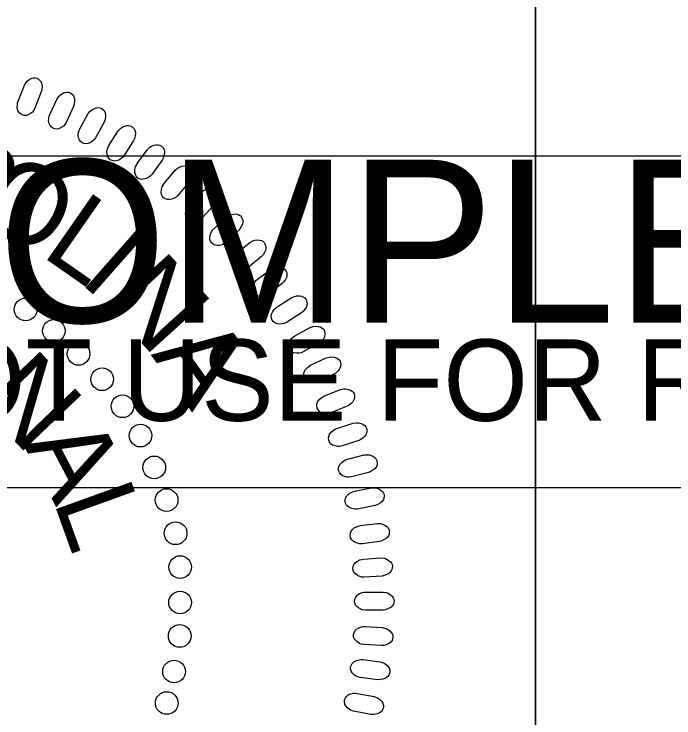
# Model space of a CAD drawing. Extents: x 505602 to 507705, y 483109 to 484209.
# Drawn here: x 507132.23 to 507178.88, y 484086.24 to 484136.03 of the extents above; entities that cross this region are included whole.
import ezdxf

# ---------------------------------------------------------------- set-up
doc = ezdxf.new("R2010")
doc.units = 0
for name, color, linetype in [('Sheet PE Seal Cell', 7, 'Continuous'), ('Sheet Profile CELL', 7, 'Continuous'), ('Sheet Sticker Incomplete CELL', 7, 'Continuous')]:
    doc.layers.add(name, color=color, linetype=linetype)

msp = doc.modelspace()

# ---------------------------------------------------------------- linework, layer by layer
at = {"layer": 'Sheet PE Seal Cell'}
for points in [[(507132.514, 484129.863), (507132.966, 484131.003), (507133.082, 484131.193), (507133.182, 484131.304), (507133.349, 484131.42), (507133.48, 484131.486), (507133.613, 484131.519), (507133.725, 484131.518), (507133.837, 484131.495), (507133.933, 484131.435), (507134.034, 484131.363), (507134.109, 484131.269), (507134.17, 484131.137), (507134.196, 484131.041), (507134.203, 484130.878), (507134.193, 484130.689), (507134.155, 484130.532), (507133.699, 484129.361), (507133.615, 484129.212), (507133.522, 484129.098), (507133.38, 484128.984), (507133.224, 484128.894), (507133.105, 484128.856), (507132.936, 484128.859), (507132.79, 484128.895), (507132.666, 484128.987), (507132.587, 484129.072), (507132.505, 484129.212), (507132.457, 484129.414), (507132.46, 484129.605), (507132.481, 484129.737)], [(507134.756, 484128.929), (507135.278, 484130.038), (507135.405, 484130.221), (507135.512, 484130.325), (507135.686, 484130.431), (507135.821, 484130.489), (507135.956, 484130.513), (507136.068, 484130.504), (507136.178, 484130.474), (507136.27, 484130.408), (507136.366, 484130.331), (507136.435, 484130.232), (507136.487, 484130.097), (507136.508, 484130), (507136.505, 484129.835), (507136.482, 484129.648), (507136.435, 484129.493), (507135.906, 484128.353), (507135.814, 484128.21), (507135.713, 484128.102), (507135.564, 484127.996), (507135.403, 484127.918), (507135.281, 484127.887), (507135.114, 484127.899), (507134.97, 484127.946), (507134.852, 484128.045), (507134.779, 484128.135), (507134.706, 484128.279), (507134.67, 484128.483), (507134.686, 484128.675), (507134.714, 484128.804)], [(507136.88, 484127.913), (507137.471, 484128.988), (507137.609, 484129.162), (507137.722, 484129.259), (507137.902, 484129.354), (507138.04, 484129.403), (507138.177, 484129.419), (507138.288, 484129.403), (507138.396, 484129.367), (507138.485, 484129.295), (507138.575, 484129.211), (507138.638, 484129.109), (507138.682, 484128.971), (507138.695, 484128.872), (507138.683, 484128.709), (507138.648, 484128.522), (507138.591, 484128.372), (507137.992, 484127.267), (507137.89, 484127.13), (507137.784, 484127.029), (507137.629, 484126.932), (507137.462, 484126.864), (507137.339, 484126.841), (507137.173, 484126.864), (507137.032, 484126.919), (507136.92, 484127.025), (507136.852, 484127.12), (507136.789, 484127.269), (507136.766, 484127.475), (507136.794, 484127.664), (507136.83, 484127.793)], [(507138.938, 484126.728), (507139.595, 484127.764), (507139.744, 484127.929), (507139.863, 484128.018), (507140.049, 484128.102), (507140.19, 484128.143), (507140.327, 484128.15), (507140.437, 484128.127), (507140.543, 484128.084), (507140.626, 484128.007), (507140.711, 484127.917), (507140.768, 484127.811), (507140.802, 484127.67), (507140.81, 484127.571), (507140.787, 484127.408), (507140.741, 484127.225), (507140.674, 484127.078), (507140.007, 484126.014), (507139.897, 484125.883), (507139.784, 484125.789), (507139.623, 484125.702), (507139.454, 484125.644), (507139.329, 484125.629), (507139.164, 484125.662), (507139.027, 484125.726), (507138.923, 484125.84), (507138.861, 484125.938), (507138.807, 484126.091), (507138.797, 484126.297), (507138.837, 484126.485), (507138.881, 484126.611)], [(507140.938, 484125.455), (507141.659, 484126.447), (507141.818, 484126.603), (507141.943, 484126.685), (507142.133, 484126.756), (507142.276, 484126.788), (507142.413, 484126.787), (507142.522, 484126.757), (507142.625, 484126.707), (507142.703, 484126.626), (507142.782, 484126.531), (507142.832, 484126.421), (507142.858, 484126.279), (507142.86, 484126.179), (507142.826, 484126.018), (507142.769, 484125.838), (507142.693, 484125.696), (507141.96, 484124.675), (507141.842, 484124.551), (507141.723, 484124.465), (507141.558, 484124.388), (507141.384, 484124.341), (507141.259, 484124.334), (507141.097, 484124.378), (507140.964, 484124.45), (507140.866, 484124.57), (507140.811, 484124.672), (507140.767, 484124.827), (507140.77, 484125.034), (507140.821, 484125.219), (507140.873, 484125.342)], [(507142.832, 484124.039), (507143.614, 484124.984), (507143.783, 484125.129), (507143.912, 484125.203), (507144.107, 484125.263), (507144.251, 484125.285), (507144.389, 484125.275), (507144.495, 484125.239), (507144.594, 484125.182), (507144.668, 484125.096), (507144.741, 484124.996), (507144.783, 484124.884), (507144.8, 484124.74), (507144.796, 484124.641), (507144.751, 484124.483), (507144.683, 484124.306), (507144.599, 484124.169), (507143.804, 484123.196), (507143.678, 484123.079), (507143.554, 484123.001), (507143.384, 484122.935), (507143.208, 484122.899), (507143.082, 484122.899), (507142.923, 484122.953), (507142.795, 484123.034), (507142.705, 484123.16), (507142.657, 484123.265), (507142.623, 484123.422), (507142.639, 484123.629), (507142.701, 484123.811), (507142.761, 484123.929)], [(507144.603, 484122.525), (507145.444, 484123.419), (507145.621, 484123.553), (507145.755, 484123.619), (507145.953, 484123.666), (507146.099, 484123.679), (507146.235, 484123.661), (507146.339, 484123.618), (507146.434, 484123.556), (507146.502, 484123.465), (507146.569, 484123.361), (507146.604, 484123.246), (507146.612, 484123.101), (507146.601, 484123.002), (507146.547, 484122.847), (507146.468, 484122.675), (507146.376, 484122.544), (507145.52, 484121.623), (507145.388, 484121.515), (507145.259, 484121.444), (507145.085, 484121.389), (507144.908, 484121.364), (507144.782, 484121.372), (507144.626, 484121.436), (507144.504, 484121.524), (507144.423, 484121.655), (507144.381, 484121.763), (507144.356, 484121.923), (507144.385, 484122.128), (507144.459, 484122.305), (507144.526, 484122.42)], [(507146.348, 484120.831), (507147.243, 484121.671), (507147.428, 484121.793), (507147.566, 484121.851), (507147.766, 484121.885), (507147.912, 484121.89), (507148.047, 484121.863), (507148.148, 484121.814), (507148.24, 484121.745), (507148.302, 484121.65), (507148.362, 484121.542), (507148.39, 484121.425), (507148.389, 484121.28), (507148.371, 484121.182), (507148.308, 484121.031), (507148.219, 484120.865), (507148.117, 484120.738), (507147.206, 484119.874), (507147.067, 484119.774), (507146.935, 484119.711), (507146.757, 484119.667), (507146.578, 484119.653), (507146.453, 484119.669), (507146.302, 484119.743), (507146.185, 484119.839), (507146.112, 484119.974), (507146.077, 484120.085), (507146.063, 484120.246), (507146.105, 484120.449), (507146.19, 484120.622), (507146.264, 484120.732)], [(507147.96, 484119.085), (507148.905, 484119.867), (507149.099, 484119.978), (507149.24, 484120.027), (507149.441, 484120.048), (507149.588, 484120.043), (507149.721, 484120.007), (507149.818, 484119.952), (507149.906, 484119.878), (507149.961, 484119.779), (507150.014, 484119.668), (507150.035, 484119.549), (507150.025, 484119.405), (507150.001, 484119.308), (507149.929, 484119.161), (507149.829, 484119.001), (507149.72, 484118.882), (507148.756, 484118.075), (507148.611, 484117.984), (507148.475, 484117.93), (507148.295, 484117.898), (507148.116, 484117.895), (507147.992, 484117.919), (507147.846, 484118.001), (507147.736, 484118.105), (507147.671, 484118.245), (507147.643, 484118.357), (507147.639, 484118.519), (507147.693, 484118.719), (507147.789, 484118.885), (507147.87, 484118.991)], [(507149.42, 484117.263), (507150.413, 484117.983), (507150.612, 484118.082), (507150.756, 484118.122), (507150.96, 484118.131), (507151.105, 484118.116), (507151.235, 484118.073), (507151.329, 484118.011), (507151.412, 484117.932), (507151.461, 484117.829), (507151.507, 484117.716), (507151.52, 484117.596), (507151.501, 484117.452), (507151.472, 484117.357), (507151.39, 484117.214), (507151.28, 484117.061), (507151.164, 484116.949), (507150.152, 484116.204), (507150.001, 484116.123), (507149.861, 484116.077), (507149.68, 484116.056), (507149.501, 484116.065), (507149.379, 484116.097), (507149.239, 484116.189), (507149.135, 484116.298), (507149.079, 484116.442), (507149.058, 484116.556), (507149.064, 484116.718), (507149.131, 484116.914), (507149.237, 484117.074), (507149.324, 484117.175)], [(507150.821, 484115.316), (507151.857, 484115.974), (507152.062, 484116.06), (507152.208, 484116.091), (507152.411, 484116.087), (507152.556, 484116.063), (507152.683, 484116.011), (507152.773, 484115.944), (507152.85, 484115.86), (507152.893, 484115.755), (507152.932, 484115.638), (507152.938, 484115.517), (507152.909, 484115.375), (507152.874, 484115.282), (507152.783, 484115.145), (507152.664, 484114.999), (507152.542, 484114.894), (507151.485, 484114.215), (507151.329, 484114.143), (507151.187, 484114.107), (507151.004, 484114.097), (507150.826, 484114.116), (507150.707, 484114.156), (507150.572, 484114.256), (507150.476, 484114.372), (507150.429, 484114.519), (507150.415, 484114.634), (507150.431, 484114.796), (507150.51, 484114.987), (507150.626, 484115.14), (507150.72, 484115.235)], [(507152.082, 484113.267), (507153.157, 484113.857), (507153.367, 484113.93), (507153.515, 484113.952), (507153.717, 484113.936), (507153.86, 484113.903), (507153.984, 484113.843), (507154.07, 484113.77), (507154.141, 484113.682), (507154.178, 484113.574), (507154.209, 484113.454), (507154.207, 484113.334), (507154.17, 484113.194), (507154.129, 484113.104), (507154.03, 484112.972), (507153.901, 484112.834), (507153.773, 484112.737), (507152.675, 484112.126), (507152.515, 484112.064), (507152.371, 484112.036), (507152.188, 484112.038), (507152.012, 484112.068), (507151.895, 484112.115), (507151.767, 484112.224), (507151.678, 484112.345), (507151.641, 484112.495), (507151.634, 484112.611), (507151.66, 484112.771), (507151.751, 484112.957), (507151.876, 484113.103), (507151.976, 484113.192)], [(507153.189, 484111.184), (507154.299, 484111.706), (507154.514, 484111.765), (507154.662, 484111.778), (507154.864, 484111.748), (507155.004, 484111.706), (507155.124, 484111.639), (507155.205, 484111.561), (507155.271, 484111.468), (507155.3, 484111.358), (507155.324, 484111.237), (507155.315, 484111.117), (507155.269, 484110.98), (507155.222, 484110.892), (507155.115, 484110.767), (507154.978, 484110.637), (507154.843, 484110.549), (507153.709, 484110.007), (507153.546, 484109.956), (507153.4, 484109.937), (507153.219, 484109.95), (507153.044, 484109.992), (507152.93, 484110.046), (507152.809, 484110.163), (507152.728, 484110.29), (507152.7, 484110.442), (507152.701, 484110.558), (507152.737, 484110.716), (507152.84, 484110.896), (507152.974, 484111.033), (507153.079, 484111.115)], [(507154.169, 484109.022), (507155.31, 484109.474), (507155.527, 484109.519), (507155.676, 484109.523), (507155.875, 484109.481), (507156.013, 484109.43), (507156.128, 484109.355), (507156.204, 484109.273), (507156.264, 484109.176), (507156.286, 484109.064), (507156.302, 484108.942), (507156.286, 484108.823), (507156.231, 484108.689), (507156.179, 484108.604), (507156.065, 484108.486), (507155.92, 484108.364), (507155.78, 484108.285), (507154.614, 484107.816), (507154.448, 484107.774), (507154.301, 484107.765), (507154.12, 484107.79), (507153.949, 484107.842), (507153.839, 484107.903), (507153.725, 484108.028), (507153.652, 484108.159), (507153.634, 484108.313), (507153.642, 484108.429), (507153.688, 484108.584), (507153.802, 484108.757), (507153.944, 484108.886), (507154.054, 484108.961)], [(507155.042, 484106.708), (507156.21, 484107.087), (507156.43, 484107.119), (507156.579, 484107.113), (507156.775, 484107.058), (507156.909, 484107), (507157.02, 484106.918), (507157.09, 484106.831), (507157.143, 484106.73), (507157.159, 484106.617), (507157.168, 484106.494), (507157.143, 484106.377), (507157.08, 484106.246), (507157.023, 484106.164), (507156.901, 484106.054), (507156.749, 484105.942), (507156.604, 484105.871), (507155.411, 484105.476), (507155.243, 484105.445), (507155.097, 484105.445), (507154.918, 484105.481), (507154.75, 484105.544), (507154.644, 484105.612), (507154.538, 484105.743), (507154.473, 484105.879), (507154.465, 484106.034), (507154.48, 484106.148), (507154.536, 484106.3), (507154.66, 484106.466), (507154.81, 484106.586), (507154.924, 484106.654)], [(507155.788, 484104.535), (507156.976, 484104.839), (507157.197, 484104.858), (507157.346, 484104.842), (507157.538, 484104.776), (507157.669, 484104.709), (507157.773, 484104.62), (507157.838, 484104.529), (507157.885, 484104.425), (507157.894, 484104.311), (507157.894, 484104.188), (507157.863, 484104.072), (507157.792, 484103.946), (507157.73, 484103.868), (507157.601, 484103.766), (507157.442, 484103.663), (507157.293, 484103.602), (507156.078, 484103.283), (507155.908, 484103.262), (507155.762, 484103.271), (507155.585, 484103.318), (507155.422, 484103.392), (507155.32, 484103.466), (507155.224, 484103.603), (507155.167, 484103.743), (507155.169, 484103.898), (507155.191, 484104.012), (507155.256, 484104.16), (507155.39, 484104.317), (507155.548, 484104.427), (507155.666, 484104.488)], [(507156.297, 484102.281), (507157.502, 484102.51), (507157.725, 484102.514), (507157.872, 484102.49), (507158.059, 484102.411), (507158.185, 484102.336), (507158.285, 484102.241), (507158.343, 484102.146), (507158.384, 484102.039), (507158.385, 484101.926), (507158.378, 484101.802), (507158.339, 484101.689), (507158.261, 484101.567), (507158.194, 484101.493), (507158.059, 484101.399), (507157.894, 484101.307), (507157.742, 484101.255), (507156.508, 484101.012), (507156.337, 484101.003), (507156.192, 484101.021), (507156.019, 484101.079), (507155.861, 484101.163), (507155.764, 484101.243), (507155.675, 484101.387), (507155.628, 484101.53), (507155.639, 484101.684), (507155.669, 484101.796), (507155.743, 484101.94), (507155.887, 484102.088), (507156.052, 484102.189), (507156.173, 484102.242)], [(507156.695, 484099.842), (507157.913, 484099.995), (507158.135, 484099.985), (507158.28, 484099.951), (507158.462, 484099.861), (507158.584, 484099.778), (507158.677, 484099.677), (507158.729, 484099.579), (507158.763, 484099.47), (507158.757, 484099.356), (507158.742, 484099.233), (507158.696, 484099.122), (507158.61, 484099.006), (507158.539, 484098.937), (507158.398, 484098.851), (507158.228, 484098.769), (507158.072, 484098.727), (507156.826, 484098.562), (507156.655, 484098.564), (507156.511, 484098.591), (507156.342, 484098.66), (507156.189, 484098.753), (507156.098, 484098.84), (507156.018, 484098.988), (507155.981, 484099.134), (507156.002, 484099.287), (507156.038, 484099.397), (507156.121, 484099.536), (507156.274, 484099.676), (507156.444, 484099.765), (507156.569, 484099.81)], [(507156.939, 484097.477), (507158.163, 484097.553), (507158.384, 484097.529), (507158.527, 484097.487), (507158.704, 484097.385), (507158.819, 484097.295), (507158.905, 484097.188), (507158.951, 484097.086), (507158.979, 484096.975), (507158.966, 484096.862), (507158.944, 484096.741), (507158.89, 484096.633), (507158.797, 484096.522), (507158.721, 484096.458), (507158.576, 484096.381), (507158.401, 484096.31), (507158.243, 484096.278), (507156.989, 484096.192), (507156.819, 484096.204), (507156.676, 484096.24), (507156.512, 484096.319), (507156.366, 484096.422), (507156.28, 484096.514), (507156.21, 484096.667), (507156.181, 484096.816), (507156.211, 484096.967), (507156.255, 484097.075), (507156.346, 484097.208), (507156.508, 484097.337), (507156.683, 484097.416), (507156.81, 484097.454)], [(507157.088, 484095.147), (507158.315, 484095.146), (507158.534, 484095.109), (507158.674, 484095.056), (507158.844, 484094.944), (507158.953, 484094.847), (507159.033, 484094.735), (507159.072, 484094.631), (507159.092, 484094.518), (507159.072, 484094.406), (507159.043, 484094.286), (507158.983, 484094.182), (507158.883, 484094.077), (507158.803, 484094.017), (507158.653, 484093.95), (507158.474, 484093.89), (507158.315, 484093.868), (507157.058, 484093.861), (507156.889, 484093.883), (507156.748, 484093.929), (507156.589, 484094.018), (507156.45, 484094.13), (507156.37, 484094.227), (507156.31, 484094.384), (507156.29, 484094.534), (507156.33, 484094.684), (507156.38, 484094.788), (507156.479, 484094.915), (507156.65, 484095.034), (507156.829, 484095.102), (507156.958, 484095.132)], [(507157.055, 484092.706), (507158.28, 484092.629), (507158.495, 484092.577), (507158.632, 484092.517), (507158.795, 484092.394), (507158.898, 484092.29), (507158.97, 484092.173), (507159.003, 484092.067), (507159.016, 484091.953), (507158.989, 484091.842), (507158.952, 484091.725), (507158.886, 484091.624), (507158.779, 484091.526), (507158.696, 484091.472), (507158.542, 484091.414), (507158.359, 484091.365), (507158.198, 484091.353), (507156.944, 484091.425), (507156.776, 484091.458), (507156.64, 484091.512), (507156.486, 484091.611), (507156.354, 484091.732), (507156.28, 484091.834), (507156.23, 484091.994), (507156.22, 484092.145), (507156.269, 484092.292), (507156.326, 484092.393), (507156.433, 484092.513), (507156.61, 484092.622), (507156.794, 484092.678), (507156.924, 484092.699)], [(507156.888, 484090.366), (507158.106, 484090.212), (507158.318, 484090.147), (507158.45, 484090.078), (507158.605, 484089.946), (507158.702, 484089.835), (507158.766, 484089.714), (507158.793, 484089.606), (507158.798, 484089.491), (507158.765, 484089.383), (507158.719, 484089.268), (507158.647, 484089.172), (507158.535, 484089.08), (507158.449, 484089.031), (507158.292, 484088.983), (507158.106, 484088.947), (507157.945, 484088.944), (507156.697, 484089.095), (507156.532, 484089.138), (507156.399, 484089.2), (507156.252, 484089.309), (507156.128, 484089.438), (507156.061, 484089.544), (507156.021, 484089.708), (507156.02, 484089.858), (507156.079, 484090.002), (507156.141, 484090.099), (507156.256, 484090.213), (507156.439, 484090.31), (507156.626, 484090.355), (507156.758, 484090.367)], [(507156.492, 484087.979), (507157.696, 484087.749), (507157.905, 484087.671), (507158.032, 484087.594), (507158.178, 484087.451), (507158.267, 484087.335), (507158.325, 484087.21), (507158.344, 484087.1), (507158.343, 484086.986), (507158.302, 484086.88), (507158.25, 484086.768), (507158.172, 484086.676), (507158.054, 484086.593), (507157.964, 484086.548), (507157.805, 484086.51), (507157.618, 484086.485), (507157.457, 484086.493), (507156.221, 484086.722), (507156.059, 484086.776), (507155.93, 484086.846), (507155.79, 484086.964), (507155.674, 484087.1), (507155.614, 484087.211), (507155.584, 484087.376), (507155.593, 484087.527), (507155.66, 484087.666), (507155.729, 484087.76), (507155.85, 484087.866), (507156.039, 484087.951), (507156.229, 484087.984), (507156.361, 484087.988)]]:
    msp.add_lwpolyline(points, close=True, dxfattribs=at)
for centre in [(507133.046, 484115.137), (507135.036, 484113.622), (507136.787, 484111.988), (507138.459, 484110.195), (507139.891, 484108.282), (507141.165, 484106.21), (507142.137, 484103.961), (507143.012, 484101.65), (507143.648, 484099.3), (507143.966, 484096.909), (507143.965, 484094.4), (507143.935, 484092.036), (507143.537, 484089.526), (507143.018, 484087.295)]:
    msp.add_circle(centre, 0.801, dxfattribs=at)
at = {"layer": 'Sheet Profile CELL'}
msp.add_line((507169.08, 484158.662), (507169.08, 484046.212), dxfattribs=at)
for points in [[(507069.03, 484158.662), (507169.08, 484158.662), (507169.08, 484046.162), (507069.03, 484046.162)], [(507169.08, 484158.662), (507269.08, 484158.662), (507269.08, 484046.162), (507169.08, 484046.162)]]:
    msp.add_lwpolyline(points, close=True, dxfattribs=at)
at = {"layer": 'Sheet Sticker Incomplete CELL'}
msp.add_lwpolyline([(507095.597, 484102.505), (507095.597, 484126.005), (507242.597, 484126.005), (507242.597, 484102.505)], close=True, dxfattribs=at)

# ---------------------------------------------------------------- texts
at = {"layer": 'Sheet PE Seal Cell'}
for s, rotation, p in [('R', 344.609, (507126.371, 484122.173)), ('O', 331.6302, (507129.326, 484121.519)), ('L', 325.1409, (507134.059, 484118.988)), ('I', 318.6515, (507136.752, 484117.135)), ('N', 312.1622, (507138.557, 484115.715)), ('A', 305.6728, (507141.877, 484111.935)), ('N', 313.6502, (507129.525, 484108.677)), ('A', 297.7707, (507132.862, 484105.596)), ('L', 289.8309, (507134.985, 484101.601))]:
    msp.add_text(s, height=5.669, rotation=rotation, dxfattribs=at).set_placement(p)
at = {"layer": 'Sheet Sticker Incomplete CELL'}
for s, height, p in [('INCOMPLETE PLANS', 11.52, (507104.547, 484114.205)), ('DO NOT USE FOR R/W ACQUISITION', 5.76, (507107.797, 484107.255))]:
    msp.add_text(s, height=height, dxfattribs=at).set_placement(p)

doc.saveas('drawing.dxf')
